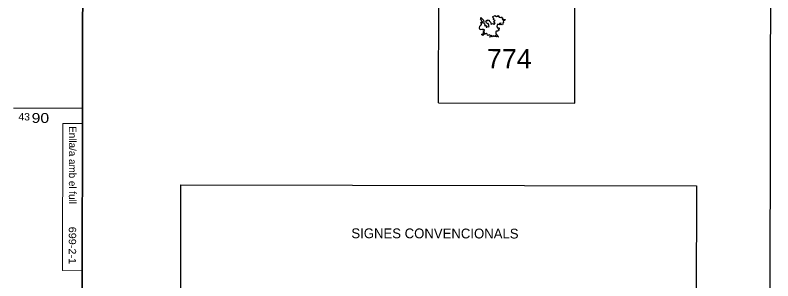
# Model space of a CAD drawing. Extents: x 483855 to 488461, y 4388206 to 4391419.
# Drawn here: x 487690 to 488461, y 4389824 to 4390095 of the extents above; entities that cross this region are included whole.
import ezdxf
from ezdxf.enums import TextEntityAlignment as Align

# ---------------------------------------------------------------- set-up
doc = ezdxf.new("R2010")
doc.units = 0
doc.header["$LTSCALE"] = 4
doc.linetypes.add('DOTTED', pattern=[1.5, 0.3, -1.2])
for name, color, linetype, lineweight in [('1', 7, 'Continuous', 13), ('2', 7, 'DOTTED', 13), ('3', 7, 'Continuous', 25)]:
    doc.layers.add(name, color=color, linetype=linetype, lineweight=lineweight)

msp = doc.modelspace()

# ---------------------------------------------------------------- linework, layer by layer
at = {"layer": '1', "lineweight": 25}
for p, q in [((488120.68, 4390005.39), (488121.71, 4390547.34)), ((488259.24, 4390005.13), (488260.27, 4390547.08)), ((488120.68, 4390005.38), (488259.24, 4390005.12)), ((487858.01, 4389921.83), (487854.99, 4388331.83)), ((487858.01, 4389921.83), (488383.01, 4389920.83)), ((488383.01, 4389920.83), (488379.99, 4388330.83))]:
    msp.add_line(p, q, dxfattribs=at)
at = {"layer": '1'}
for p, q in [((487687.9, 4390000), (487758.17, 4390000)), ((487757.86, 4389834.52), (487737.86, 4389834.56))]:
    msp.add_line(p, q, dxfattribs=at)
at = {"layer": '1', "lineweight": 25}
msp.add_lwpolyline([(483860.86, 4391419.44), (488460.85, 4391410.69), (488454.76, 4388205.69), (483854.77, 4388214.44)], close=True, dxfattribs=at)
at = {"layer": '1', "lineweight": 35}
msp.add_lwpolyline([(484045.03, 4391144.08), (487760.33, 4391137.02), (487755.66, 4388682.02), (484040.36, 4388689.09)], close=True, dxfattribs=at)
at = {"layer": '1'}
msp.add_lwpolyline([(487758.14, 4389984.52), (487738.14, 4389984.56), (487737.86, 4389834.56)], dxfattribs=at)
at = {"layer": '3'}
for points in [[(488177.18, 4390088.36), (488178.05, 4390089.43), (488176.47, 4390089.79), (488176.97, 4390090.83), (488176.74, 4390091.48), (488175.64, 4390091.83), (488176.26, 4390092.61), (488175.9, 4390093.43), (488177.38, 4390093.98), (488177.72, 4390094.53), (488179.51, 4390093.45)], [(488164.78, 4390080.1), (488162.98, 4390079.83), (488162.37, 4390081.49), (488162.55, 4390083.4), (488163.47, 4390084.61), (488164.21, 4390084.85), (488164.06, 4390085.5), (488164.76, 4390085.51), (488163.92, 4390086.45), (488164.08, 4390087.06), (488163.51, 4390087.51), (488165.22, 4390086.85), (488165.32, 4390087.83), (488164.31, 4390088.74), (488164.23, 4390089.71), (488163.4, 4390090.6), (488163.48, 4390091.29)], [(488163.48, 4390091.29), (488163.66, 4390092.48), (488166.32, 4390089.73), (488166.68, 4390087.35), (488166.43, 4390086.61), (488167.11, 4390086.42), (488167.64, 4390084.95), (488167.32, 4390084.03), (488168.9, 4390084.3), (488169.04, 4390082.44), (488169.71, 4390082.48), (488170.11, 4390083.14), (488171.79, 4390082.78), (488172, 4390083.54)], [(488172, 4390083.54), (488171.21, 4390084.65), (488171.71, 4390085.29), (488170.75, 4390086.6), (488170.36, 4390086.32), (488168.87, 4390086.84), (488169.37, 4390087.61), (488168.82, 4390088.35), (488168.25, 4390088.34), (488169.56, 4390089.62), (488170.46, 4390088.97), (488171.04, 4390089.99)], [(488171.04, 4390089.99), (488172.31, 4390089.16), (488172.17, 4390088.85), (488174.01, 4390086.98), (488173.79, 4390086.44), (488174.11, 4390085.13), (488174.48, 4390085.87), (488175.97, 4390086.36), (488176.05, 4390085.86), (488176.92, 4390085.8), (488177.22, 4390085.19), (488178.05, 4390086.87), (488176.86, 4390087.52), (488176.94, 4390088.42), (488177.18, 4390088.36)], [(488179.51, 4390093.45), (488179.72, 4390093.76), (488180.02, 4390093.3), (488180.44, 4390093.66), (488181.4, 4390093.55), (488181.06, 4390093.94), (488181.39, 4390094.35), (488182.32, 4390092.8), (488183.88, 4390092.33), (488184.54, 4390092.96), (488185.07, 4390091.85), (488186.24, 4390091.67), (488185.39, 4390091.01), (488185.8, 4390090.32), (488188.44, 4390090.44), (488188.42, 4390089.85), (488186.41, 4390088.09), (488186.58, 4390087.3), (488186.04, 4390086.69), (488186.1, 4390085.87)], [(488186.1, 4390085.87), (488185.53, 4390084.83), (488184.77, 4390085.05), (488184.22, 4390084.69), (488183.84, 4390086.8), (488183.51, 4390086.08), (488182.73, 4390086.25), (488182.97, 4390085.53), (488182.36, 4390085.72), (488182.19, 4390085.29), (488181.39, 4390085.07), (488180.62, 4390085.45), (488180.85, 4390084.8), (488180.13, 4390084.7), (488179.75, 4390083.17), (488180.1, 4390082.84), (488180.1, 4390081.86)], [(488167.94, 4390075.9), (488166.06, 4390074.47), (488166.07, 4390073.98), (488164.57, 4390074.67), (488164.74, 4390075.48), (488167.77, 4390076.24), (488166.71, 4390076.65), (488167.11, 4390077.05), (488166.78, 4390077.87), (488167.11, 4390078.53), (488165.87, 4390078.44), (488165.93, 4390078.75), (488166.48, 4390078.55), (488167.33, 4390079.16), (488167.34, 4390079.82), (488166.29, 4390080.25), (488164.78, 4390080.1)], [(488180.1, 4390081.86), (488181.87, 4390081.8), (488182.29, 4390081.32), (488182.21, 4390080.75), (488181.19, 4390079.7), (488181.54, 4390079.27), (488180.98, 4390078.59), (488181.23, 4390078.42), (488179.45, 4390078.51), (488179, 4390077.92), (488178.89, 4390075.68), (488180.67, 4390073.52), (488179.91, 4390073.39), (488179.81, 4390072.76), (488179.43, 4390072.93), (488178.96, 4390072.52), (488179.03, 4390073.52), (488178.29, 4390073.85)], [(488178.29, 4390073.85), (488178.46, 4390073.52), (488177.52, 4390073.04), (488176.62, 4390073.52), (488176.1, 4390072.63), (488175.06, 4390073.15), (488174.61, 4390073.88), (488173.01, 4390073.78), (488172.63, 4390074.55), (488171.56, 4390074.45), (488171.16, 4390074.01), (488170.42, 4390074.27), (488170.21, 4390075.55), (488169.51, 4390076.03), (488168.97, 4390075.94), (488168.65, 4390075.2), (488167.94, 4390075.9)]]:
    msp.add_lwpolyline(points, dxfattribs=at)
for points in [[(488182.18, 4390079.89), (488182.62, 4390079.69), (488181.82, 4390079.76)], [(488183.17, 4390085.17), (488182.97, 4390084.86), (488182.89, 4390085.32)], [(488165.94, 4390076.87), (488166.15, 4390076.66), (488165.77, 4390076.64)], [(488172.52, 4390072.53), (488172.9, 4390073.05), (488173.22, 4390072.8), (488172.72, 4390072.33)], [(488174.13, 4390072.88), (488174.16, 4390073.26), (488174.82, 4390072.77)], [(488181.03, 4390073.23), (488181.68, 4390072.71), (488180.78, 4390072.22), (488180.58, 4390073.1)]]:
    msp.add_lwpolyline(points, close=True, dxfattribs=at)

# ---------------------------------------------------------------- texts
at = {"layer": '2', "width": 1.05}
msp.add_text('774', height=19.5, rotation=359.891, dxfattribs=at).set_placement((488192.53, 4390040.63), align=Align.CENTER)
at = {"layer": '2'}
for s, height, width, p in [('43', 7.5, 1.05, (487692.89, 4389987.5)), ('90  ', 10, 1.2, (487706.34, 4389985))]:
    msp.add_text(s, height=height, dxfattribs=dict(at, width=width)).set_placement(p)
msp.add_text('Enlla/a amb el full', height=7.5, rotation=269.891, dxfattribs=at).set_placement((487744.39, 4389981.67))
at = {"layer": '2', "width": 1.1}
msp.add_text('699-2-1', height=7.5, rotation=269.891, dxfattribs=at).set_placement((487744.19, 4389879.3))
at = {"layer": '2'}
msp.add_text('SIGNES CONVENCIONALS', height=10, rotation=359.891, dxfattribs=at).set_placement((488116.91, 4389867.44), align=Align.CENTER)

doc.saveas('drawing.dxf')
